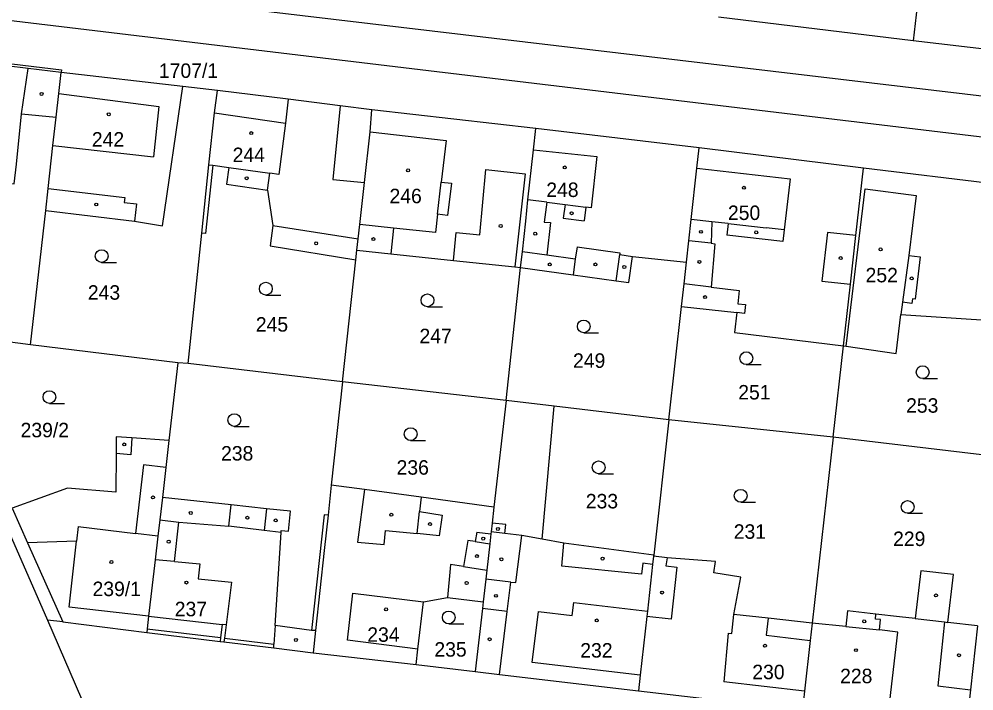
# Model space of a CAD drawing. Extents: x -724107 to -720612, y -1045267 to -1038441.
# Drawn here: x -722932.3 to -722820.2, y -1042174.7 to -1042095.8 of the extents above; entities that cross this region are included whole.
import ezdxf

# ---------------------------------------------------------------- set-up
doc = ezdxf.new("R2010")
doc.units = 0
for name, color, linetype in [('Hranice parcel', 7, 'Continuous'), ('Parcelní čísla', 7, 'Continuous'), ('Vnitřní kresba', 7, 'Continuous'), ('Značky budov', 7, 'Continuous'), ('Značky kultur', 7, 'Continuous')]:
    doc.layers.add(name, color=color, linetype=linetype)

msp = doc.modelspace()

# ---------------------------------------------------------------- linework, layer by layer
at = {"layer": 'Hranice parcel'}
for p, q in [((-722823.15, -1042063.63), (-722827.33, -1042098.38)), ((-722961.44, -1042092.63), (-722614.7, -1042134.22)), ((-722827.33, -1042098.38), (-722850.16, -1042095.63)), ((-722958.94, -1042098.3), (-722928.96, -1042166.43)), ((-722810.31, -1042100.42), (-722827.33, -1042098.38)), ((-722913.09, -1042103.75), (-722927.35, -1042102.12)), ((-722909.01, -1042104.22), (-722913.09, -1042103.75)), ((-722871.64, -1042108.71), (-722890.9, -1042106.49)), ((-722852.44, -1042110.98), (-722871.64, -1042108.71)), ((-722833.16, -1042113.36), (-722852.44, -1042110.98)), ((-722814.35, -1042115.64), (-722833.16, -1042113.36)), ((-722930.96, -1042134.09), (-722929.17, -1042118.32)), ((-722892.75, -1042124.1), (-722892.63, -1042123)), ((-722894.33, -1042138.46), (-722892.75, -1042124.1)), ((-722875.11, -1042140.62), (-722873.41, -1042125.02)), ((-722856, -1042142.89), (-722854.52, -1042129.59)), ((-722930.96, -1042134.09), (-722942.26, -1042132.6)), ((-722913.66, -1042136.23), (-722930.96, -1042134.09)), ((-722836.71, -1042144.96), (-722835.5, -1042134.21)), ((-722913.66, -1042136.23), (-722914.71, -1042145.34)), ((-722912.46, -1042136.29), (-722913.66, -1042136.23)), ((-722894.33, -1042138.46), (-722912.46, -1042136.29)), ((-722894.33, -1042138.46), (-722895.65, -1042150.57)), ((-722875.11, -1042140.62), (-722894.33, -1042138.46)), ((-722875.11, -1042140.62), (-722876.54, -1042153.16)), ((-722869.47, -1042141.29), (-722875.11, -1042140.62)), ((-722856, -1042142.89), (-722869.47, -1042141.29)), ((-722856, -1042142.89), (-722857.79, -1042158.79)), ((-722836.71, -1042144.96), (-722856, -1042142.89)), ((-722836.71, -1042144.96), (-722839.18, -1042166.79)), ((-722817.33, -1042147.24), (-722836.71, -1042144.96)), ((-722857.79, -1042158.79), (-722857.81, -1042158.94)), ((-722927.18, -1042166.65), (-722928.96, -1042166.43)), ((-722928.96, -1042166.43), (-722924.33, -1042177.14)), ((-722927.18, -1042166.65), (-722917.31, -1042167.89)), ((-722897.51, -1042167.65), (-722897.79, -1042170.26)), ((-722897.79, -1042170.26), (-722885.69, -1042171.66)), ((-722885.69, -1042171.66), (-722878.74, -1042172.47)), ((-722859.57, -1042174.72), (-722840.31, -1042176.96))]:
    msp.add_line(p, q, dxfattribs=at)
for points in [[(-722957.38, -1042098.49), (-722957.5, -1042098.17), (-722927.33, -1042101.81), (-722927.35, -1042102.12)], [(-722941.44, -1042100.39), (-722942.83, -1042111.63), (-722939.2, -1042112.07), (-722939.41, -1042113.91), (-722938.26, -1042114.08), (-722938.3, -1042114.55), (-722934.94, -1042114.87), (-722932.89, -1042115.21), (-722932.59, -1042112.9), (-722932.01, -1042106.98), (-722927.96, -1042107.37)], [(-722927.35, -1042102.12), (-722931.22, -1042101.64), (-722941.44, -1042100.39)], [(-722927.96, -1042107.37), (-722927.64, -1042104.6), (-722927.35, -1042102.12)], [(-722929.17, -1042118.32), (-722918.76, -1042119.59), (-722915.45, -1042120.13), (-722913.09, -1042103.75)], [(-722910.01, -1042112.95), (-722909.37, -1042106.86), (-722909.01, -1042104.22)], [(-722890.9, -1042106.49), (-722894.61, -1042106.02), (-722900.7, -1042105.26), (-722909.01, -1042104.22)], [(-722892.63, -1042123), (-722892.48, -1042121.67), (-722892.29, -1042119.97), (-722891.75, -1042115.04), (-722891.09, -1042109.07), (-722890.9, -1042106.49)], [(-722929.17, -1042118.32), (-722928.88, -1042115.73), (-722928.34, -1042110.68), (-722927.96, -1042107.37)], [(-722873.41, -1042125.02), (-722873.21, -1042123.16), (-722872.82, -1042119.59), (-722872.55, -1042117.08), (-722871.92, -1042111.21), (-722871.64, -1042108.71)], [(-722853.93, -1042124.38), (-722853.66, -1042121.88), (-722853.38, -1042119.37), (-722852.71, -1042113.37), (-722852.44, -1042110.98)], [(-722912.46, -1042136.29), (-722910.85, -1042120.98), (-722910.01, -1042112.95)], [(-722910.01, -1042112.95), (-722909.56, -1042113.01), (-722907.68, -1042113.27), (-722907.96, -1042115.25), (-722903.14, -1042115.92), (-722902.5, -1042120.1), (-722902.84, -1042122.49), (-722892.75, -1042124.1)], [(-722835.5, -1042134.21), (-722834.69, -1042126.98), (-722834.05, -1042121.27), (-722833.16, -1042113.36)], [(-722892.63, -1042123), (-722888.65, -1042123.42), (-722881.31, -1042124.19), (-722874.11, -1042124.95), (-722873.41, -1042125.02)], [(-722873.41, -1042125.02), (-722867.25, -1042125.88), (-722862.2, -1042126.58), (-722860.72, -1042126.79), (-722860.29, -1042123.71), (-722853.93, -1042124.38)], [(-722854.52, -1042129.59), (-722854.22, -1042126.93), (-722853.93, -1042124.38)], [(-722854.52, -1042129.59), (-722848.02, -1042130.31), (-722848.28, -1042132.66), (-722835.5, -1042134.21)], [(-722835.5, -1042134.21), (-722835.2, -1042134.25), (-722829.33, -1042135.11), (-722828.75, -1042130.54), (-722817.52, -1042131.27), (-722816.05, -1042131.41)], [(-722857.79, -1042158.79), (-722868.35, -1042157.41), (-722870.88, -1042156.94), (-722869.47, -1042141.29)], [(-722914.71, -1042145.34), (-722919.05, -1042145.02), (-722920.9, -1042144.89), (-722920.92, -1042146.88), (-722920.96, -1042151.42), (-722926.61, -1042150.94), (-722933.1, -1042153.28)], [(-722914.71, -1042145.34), (-722915.07, -1042148.51), (-722915.48, -1042152.05)], [(-722895.65, -1042150.57), (-722896.03, -1042154.12), (-722896.49, -1042158.27), (-722897.51, -1042167.65)], [(-722876.54, -1042153.16), (-722885.09, -1042152), (-722891.73, -1042151.1), (-722895.65, -1042150.57)], [(-722915.48, -1042152.05), (-722915.79, -1042154.67), (-722916, -1042156.56), (-722916.33, -1042159.36), (-722917.09, -1042165.96), (-722917.26, -1042167.44), (-722917.31, -1042167.89)], [(-722897.51, -1042167.65), (-722897.95, -1042167.64), (-722902.24, -1042167.08), (-722901.53, -1042156.13), (-722901.52, -1042155.91), (-722900.66, -1042156), (-722900.42, -1042153.65), (-722903.26, -1042153.35), (-722907.41, -1042152.91), (-722915.48, -1042152.05)], [(-722933.1, -1042153.28), (-722931.3, -1042157.34), (-722927.18, -1042166.65)], [(-722876.54, -1042153.16), (-722876.76, -1042155.03), (-722876.88, -1042156.05), (-722876.9, -1042156.29), (-722877.03, -1042157.48), (-722877.38, -1042160.56), (-722877.51, -1042161.62), (-722877.8, -1042164.27)], [(-722857.81, -1042158.94), (-722857.91, -1042159.88), (-722858.53, -1042165.39), (-722858.6, -1042166), (-722859.38, -1042172.91), (-722859.57, -1042174.72)], [(-722839.18, -1042166.79), (-722844.35, -1042166.21), (-722848.38, -1042165.76), (-722847.57, -1042161.37), (-722850.74, -1042160.88), (-722850.53, -1042159.56), (-722856.21, -1042159.12), (-722857.81, -1042158.94)], [(-722819.76, -1042167.1), (-722823.26, -1042166.71), (-722822.6, -1042161.07), (-722826.41, -1042160.63), (-722827.07, -1042166.26), (-722828.92, -1042166.04), (-722831.69, -1042165.72), (-722835.02, -1042165.33), (-722835.24, -1042167.2), (-722839.18, -1042166.79)], [(-722885.69, -1042171.66), (-722885.47, -1042169.83), (-722884.8, -1042164.28), (-722881.99, -1042163.76), (-722877.8, -1042164.27)], [(-722877.8, -1042164.27), (-722877.9, -1042165.07), (-722878.74, -1042172.47)], [(-722839.18, -1042166.79), (-722839.41, -1042168.81), (-722840.08, -1042174.77), (-722840.31, -1042176.96)], [(-722819.76, -1042167.1), (-722820.58, -1042174.6), (-722821.09, -1042179.25)], [(-722917.31, -1042167.89), (-722908.71, -1042168.94), (-722908.26, -1042168.99), (-722902.41, -1042169.7), (-722897.79, -1042170.26)], [(-722878.74, -1042172.47), (-722875.91, -1042172.8), (-722859.57, -1042174.72)]]:
    msp.add_lwpolyline(points, dxfattribs=at)
at = {"layer": 'Vnitřní kresba'}
for p, q in [((-722788.05, -1042108.59), (-722963.56, -1042087.8)), ((-722932.01, -1042106.98), (-722931.22, -1042101.64)), ((-722927.64, -1042104.6), (-722915.89, -1042106.1)), ((-722900.7, -1042105.26), (-722901.02, -1042108.05)), ((-722915.89, -1042106.1), (-722916.53, -1042112.04)), ((-722894.61, -1042106.02), (-722895.48, -1042114.67)), ((-722909.37, -1042106.86), (-722901.02, -1042108.05)), ((-722901.02, -1042108.05), (-722901.8, -1042114.09)), ((-722891.09, -1042109.07), (-722882.16, -1042110.12)), ((-722928.34, -1042110.68), (-722916.53, -1042112.04)), ((-722882.16, -1042110.12), (-722882.73, -1042114.99)), ((-722871.92, -1042111.21), (-722864.45, -1042112)), ((-722864.45, -1042112), (-722865.11, -1042118.02)), ((-722909.56, -1042113.01), (-722910.41, -1042121.02)), ((-722907.68, -1042113.27), (-722902.87, -1042113.94)), ((-722852.71, -1042113.37), (-722841.75, -1042114.62)), ((-722903.14, -1042115.92), (-722902.87, -1042113.94)), ((-722901.8, -1042114.09), (-722902.87, -1042113.94)), ((-722878.22, -1042121.2), (-722877.49, -1042113.51)), ((-722877.49, -1042113.51), (-722872.87, -1042114.01)), ((-722872.87, -1042114.01), (-722874.11, -1042124.95)), ((-722895.48, -1042114.67), (-722891.75, -1042115.04)), ((-722883.17, -1042118.76), (-722882.73, -1042114.99)), ((-722882.73, -1042114.99), (-722881.54, -1042115.13)), ((-722881.54, -1042115.13), (-722881.98, -1042118.9)), ((-722841.75, -1042114.62), (-722842.48, -1042120.61)), ((-722928.88, -1042115.73), (-722919.89, -1042116.79)), ((-722919.89, -1042116.79), (-722919.96, -1042117.4)), ((-722835.2, -1042134.25), (-722832.96, -1042115.78)), ((-722832.96, -1042115.78), (-722826.97, -1042116.57)), ((-722826.97, -1042116.57), (-722827.84, -1042123.59)), ((-722919.96, -1042117.4), (-722918.53, -1042117.53)), ((-722918.53, -1042117.53), (-722918.76, -1042119.59)), ((-722870.34, -1042117.36), (-722872.55, -1042117.08)), ((-722870.34, -1042117.36), (-722870.63, -1042119.71)), ((-722870.34, -1042117.36), (-722868.2, -1042117.63)), ((-722868.2, -1042117.63), (-722868.4, -1042119.22)), ((-722868.2, -1042117.63), (-722865.77, -1042117.94)), ((-722865.77, -1042117.94), (-722865.97, -1042119.54)), ((-722865.11, -1042118.02), (-722865.77, -1042117.94)), ((-722883.17, -1042118.76), (-722883.42, -1042120.91)), ((-722881.98, -1042118.9), (-722883.17, -1042118.76)), ((-722902.5, -1042120.1), (-722892.48, -1042121.67)), ((-722888.33, -1042120.39), (-722892.29, -1042119.97)), ((-722870.63, -1042119.71), (-722869.9, -1042119.75)), ((-722869.9, -1042119.75), (-722870.33, -1042123.56)), ((-722868.4, -1042119.22), (-722865.97, -1042119.54)), ((-722850.98, -1042119.64), (-722853.38, -1042119.37)), ((-722850.98, -1042119.64), (-722851.02, -1042122.18)), ((-722849.03, -1042119.87), (-722850.98, -1042119.64)), ((-722849.03, -1042119.87), (-722849.18, -1042121.21)), ((-722849.03, -1042119.87), (-722844.59, -1042120.37)), ((-722910.41, -1042121.02), (-722910.85, -1042120.98)), ((-722888.33, -1042120.39), (-722888.65, -1042123.42)), ((-722883.42, -1042120.91), (-722888.33, -1042120.39)), ((-722881.31, -1042124.19), (-722880.97, -1042120.91)), ((-722880.97, -1042120.91), (-722878.22, -1042121.2)), ((-722842.64, -1042121.96), (-722849.18, -1042121.21)), ((-722842.48, -1042120.61), (-722844.59, -1042120.37)), ((-722842.48, -1042120.61), (-722842.64, -1042121.96)), ((-722837.37, -1042120.9), (-722838.03, -1042126.61)), ((-722834.05, -1042121.27), (-722837.37, -1042120.9)), ((-722851.02, -1042122.18), (-722853.66, -1042121.88)), ((-722851.02, -1042122.18), (-722850.62, -1042122.23)), ((-722850.62, -1042122.23), (-722851.02, -1042127.32)), ((-722870.33, -1042123.56), (-722873.21, -1042123.16)), ((-722866.79, -1042122.58), (-722866.99, -1042124.03)), ((-722866.79, -1042122.58), (-722861.75, -1042123.29)), ((-722862.2, -1042126.58), (-722861.78, -1042123.5)), ((-722861.75, -1042123.29), (-722861.78, -1042123.5)), ((-722861.78, -1042123.5), (-722860.29, -1042123.71)), ((-722866.99, -1042124.03), (-722870.33, -1042123.56)), ((-722866.99, -1042124.03), (-722867.25, -1042125.88)), ((-722827.84, -1042123.59), (-722828.56, -1042129.1)), ((-722827.84, -1042123.59), (-722826.49, -1042123.75)), ((-722826.49, -1042123.75), (-722827.1, -1042128.75)), ((-722838.03, -1042126.61), (-722834.69, -1042126.98)), ((-722851.02, -1042127.32), (-722854.22, -1042126.93)), ((-722851.02, -1042127.32), (-722847.74, -1042127.72)), ((-722847.74, -1042127.72), (-722847.91, -1042129.28)), ((-722828.56, -1042129.1), (-722828.75, -1042130.54)), ((-722827.49, -1042129.24), (-722828.56, -1042129.1)), ((-722827.4, -1042128.71), (-722827.49, -1042129.24)), ((-722827.1, -1042128.75), (-722827.4, -1042128.71)), ((-722847.91, -1042129.28), (-722847.01, -1042129.38)), ((-722847.01, -1042129.38), (-722847.12, -1042130.41)), ((-722847.12, -1042130.41), (-722848.02, -1042130.31)), ((-722919.05, -1042145.02), (-722919.2, -1042147.01)), ((-722919.2, -1042147.01), (-722920.92, -1042146.88)), ((-722917.71, -1042148.21), (-722918.63, -1042156.25)), ((-722915.07, -1042148.51), (-722917.71, -1042148.21)), ((-722891.73, -1042151.1), (-722892.56, -1042157.27)), ((-722885.09, -1042152), (-722885.27, -1042153.69)), ((-722907.67, -1042155.41), (-722907.41, -1042152.91)), ((-722903.26, -1042153.35), (-722903.53, -1042155.92)), ((-722885.55, -1042156.26), (-722885.27, -1042153.69)), ((-722885.27, -1042153.69), (-722882.63, -1042154.11)), ((-722915.79, -1042154.67), (-722913.53, -1042154.91)), ((-722914.04, -1042159.53), (-722913.53, -1042154.91)), ((-722913.53, -1042154.91), (-722907.67, -1042155.41)), ((-722896.48, -1042154.07), (-722897.95, -1042167.64)), ((-722896.03, -1042154.12), (-722896.48, -1042154.07)), ((-722882.63, -1042154.11), (-722882.99, -1042156.52)), ((-722925.38, -1042155.45), (-722925.56, -1042157.14)), ((-722925.38, -1042155.45), (-722918.63, -1042156.25)), ((-722903.53, -1042155.92), (-722907.67, -1042155.41)), ((-722901.53, -1042156.13), (-722903.53, -1042155.92)), ((-722889.43, -1042157.55), (-722889.28, -1042155.92)), ((-722889.28, -1042155.92), (-722885.55, -1042156.26)), ((-722875.27, -1042156.25), (-722876.88, -1042156.05)), ((-722875.14, -1042155.21), (-722876.76, -1042155.03)), ((-722875.27, -1042156.25), (-722875.14, -1042155.21)), ((-722925.56, -1042157.14), (-722931.3, -1042157.34)), ((-722926.41, -1042164.91), (-722925.56, -1042157.14)), ((-722916, -1042156.56), (-722918.63, -1042156.25)), ((-722882.99, -1042156.52), (-722885.55, -1042156.26)), ((-722879.63, -1042157.07), (-722880.11, -1042160.14)), ((-722878.75, -1042157.21), (-722879.63, -1042157.07)), ((-722878.56, -1042156.1), (-722878.75, -1042157.21)), ((-722878.56, -1042156.1), (-722876.9, -1042156.29)), ((-722873.28, -1042156.5), (-722875.27, -1042156.25)), ((-722873.97, -1042162.03), (-722873.28, -1042156.5)), ((-722870.88, -1042156.94), (-722873.28, -1042156.5)), ((-722892.56, -1042157.27), (-722889.43, -1042157.55)), ((-722878.75, -1042157.21), (-722877.03, -1042157.48)), ((-722868.58, -1042160.11), (-722868.35, -1042157.41)), ((-722914.04, -1042159.53), (-722916.33, -1042159.36)), ((-722856.21, -1042159.12), (-722856.38, -1042160.06)), ((-722914.04, -1042159.53), (-722911.09, -1042159.83)), ((-722911.09, -1042159.83), (-722911.29, -1042161.58)), ((-722881.69, -1042160.35), (-722881.99, -1042163.76)), ((-722881.64, -1042159.9), (-722881.69, -1042160.35)), ((-722880.11, -1042160.14), (-722881.64, -1042159.9)), ((-722880.11, -1042160.14), (-722877.38, -1042160.56)), ((-722859.2, -1042161.04), (-722868.58, -1042160.11)), ((-722859.07, -1042159.75), (-722859.2, -1042161.04)), ((-722857.91, -1042159.88), (-722859.07, -1042159.75)), ((-722856.38, -1042160.06), (-722855.08, -1042160.2)), ((-722855.08, -1042160.2), (-722855.75, -1042166.32)), ((-722911.29, -1042161.58), (-722907.35, -1042161.99)), ((-722874.56, -1042161.96), (-722877.51, -1042161.62)), ((-722907.35, -1042161.99), (-722908, -1042166.99)), ((-722874.99, -1042165.4), (-722874.56, -1042161.96)), ((-722874.56, -1042161.96), (-722873.97, -1042162.03)), ((-722893.75, -1042168.79), (-722893.11, -1042163.27)), ((-722893.11, -1042163.27), (-722884.8, -1042164.28)), ((-722917.09, -1042165.96), (-722926.41, -1042164.91)), ((-722867.36, -1042165.87), (-722867.18, -1042164.35)), ((-722867.18, -1042164.35), (-722858.53, -1042165.39)), ((-722917.09, -1042165.96), (-722908.45, -1042166.94)), ((-722874.99, -1042165.4), (-722877.9, -1042165.07)), ((-722875.91, -1042172.8), (-722874.99, -1042165.4)), ((-722872.04, -1042171.42), (-722871.33, -1042165.4)), ((-722871.33, -1042165.4), (-722867.36, -1042165.87)), ((-722855.75, -1042166.32), (-722858.6, -1042166)), ((-722848.63, -1042168.01), (-722848.38, -1042165.76)), ((-722831.76, -1042166.3), (-722831.69, -1042165.72)), ((-722908.45, -1042166.94), (-722908.65, -1042168.49)), ((-722908, -1042166.99), (-722908.45, -1042166.94)), ((-722908, -1042166.99), (-722908.2, -1042168.54)), ((-722902.24, -1042167.08), (-722902.39, -1042169.25)), ((-722844.35, -1042166.21), (-722844.58, -1042168.19)), ((-722835.24, -1042167.2), (-722831.29, -1042167.59)), ((-722831.15, -1042166.37), (-722831.76, -1042166.3)), ((-722831.29, -1042167.59), (-722831.15, -1042166.37)), ((-722827.07, -1042166.26), (-722823.63, -1042166.65)), ((-722823.63, -1042166.65), (-722824.43, -1042174.13)), ((-722823.63, -1042166.65), (-722823.26, -1042166.71)), ((-722917.26, -1042167.44), (-722908.65, -1042168.49)), ((-722849.03, -1042167.97), (-722849.55, -1042173.68)), ((-722849.03, -1042167.97), (-722848.63, -1042168.01)), ((-722844.58, -1042168.19), (-722839.41, -1042168.81)), ((-722829.11, -1042167.84), (-722831.29, -1042167.59)), ((-722830.05, -1042175.94), (-722829.11, -1042167.84)), ((-722908.65, -1042168.49), (-722908.71, -1042168.94)), ((-722908.2, -1042168.54), (-722908.26, -1042168.99)), ((-722908.2, -1042168.54), (-722902.39, -1042169.25)), ((-722902.41, -1042169.7), (-722902.39, -1042169.25)), ((-722885.47, -1042169.83), (-722893.75, -1042168.79)), ((-722859.38, -1042172.91), (-722872.04, -1042171.42)), ((-722840.08, -1042174.77), (-722849.55, -1042173.68)), ((-722824.43, -1042174.13), (-722820.58, -1042174.6))]:
    msp.add_line(p, q, dxfattribs=at)
at = {"layer": 'Značky budov'}
for centre in [(-722929.66, -1042104.64), (-722921.77, -1042107.03), (-722905.05, -1042109.23), (-722886.62, -1042113.61), (-722868.23, -1042113.27), (-722905.58, -1042114.54), (-722847.2, -1042115.65), (-722923.25, -1042117.62), (-722867.42, -1042118.65), (-722875.75, -1042120.15), (-722871.7, -1042121.05), (-722852.25, -1042120.83), (-722845.75, -1042120.89), (-722897.42, -1042122.18), (-722890.69, -1042121.69), (-722831.15, -1042122.89), (-722869.99, -1042124.66), (-722864.63, -1042124.66), (-722852.42, -1042124.36), (-722835.83, -1042123.92), (-722861.24, -1042124.96), (-722827.49, -1042126.3), (-722851.75, -1042128.49), (-722919.96, -1042145.8), (-722916.58, -1042152.02), (-722912.15, -1042153.85), (-722905.5, -1042154.41), (-722902.17, -1042154.72), (-722888.6, -1042154.06), (-722884.05, -1042155.16), (-722876.08, -1042155.73), (-722914.74, -1042157.22), (-722877.8, -1042156.86), (-722878.55, -1042158.91), (-722875.67, -1042159.29), (-722863.79, -1042159.21), (-722921.46, -1042159.61), (-722912.65, -1042162.02), (-722879.75, -1042162.07), (-722876.32, -1042163.58), (-722856.8, -1042163.2), (-722824.64, -1042163.53), (-722889.21, -1042165.17), (-722864.47, -1042166.47), (-722833.07, -1042166.58), (-722899.8, -1042168.76), (-722877.05, -1042168.67), (-722844.72, -1042169.45), (-722834.05, -1042169.96), (-722821.94, -1042170.56)]:
    msp.add_circle(centre, 0.175, dxfattribs=at)
at = {"layer": 'Značky kultur'}
for p, q in [((-722922.61, -1042124.43), (-722920.86, -1042124.43)), ((-722903.33, -1042128.26), (-722901.58, -1042128.26)), ((-722884.35, -1042129.62), (-722882.6, -1042129.62)), ((-722866, -1042132.69), (-722864.25, -1042132.69)), ((-722846.91, -1042136.42), (-722845.16, -1042136.42)), ((-722826.2, -1042138.06), (-722824.45, -1042138.06)), ((-722928.74, -1042140.99), (-722926.99, -1042140.99)), ((-722907.03, -1042143.69), (-722905.28, -1042143.69)), ((-722886.33, -1042145.34), (-722884.58, -1042145.34)), ((-722864.25, -1042149.24), (-722862.5, -1042149.24)), ((-722847.57, -1042152.58), (-722845.82, -1042152.58)), ((-722827.97, -1042153.89), (-722826.22, -1042153.89)), ((-722881.85, -1042166.87), (-722880.1, -1042166.87))]:
    msp.add_line(p, q, dxfattribs=at)
for centre in [(-722922.61, -1042123.68), (-722903.33, -1042127.51), (-722884.35, -1042128.87), (-722866, -1042131.94), (-722846.91, -1042135.67), (-722826.2, -1042137.31), (-722928.74, -1042140.24), (-722907.03, -1042142.94), (-722886.33, -1042144.59), (-722864.25, -1042148.49), (-722847.57, -1042151.83), (-722827.97, -1042153.14), (-722881.85, -1042166.12)]:
    msp.add_circle(centre, 0.75, dxfattribs=at)

# ---------------------------------------------------------------- texts
at = {"layer": 'Parcelní čísla'}
for s, p in [('1707/1', (-722915.89, -1042102.75)), ('242', (-722923.76, -1042110.82)), ('244', (-722907.23, -1042112.64)), ('248', (-722870.4, -1042116.74)), ('246', (-722888.81, -1042117.47)), ('250', (-722849.07, -1042119.44)), ('252', (-722832.91, -1042126.76)), ('243', (-722924.23, -1042128.8)), ('245', (-722904.51, -1042132.55)), ('247', (-722885.29, -1042133.91)), ('249', (-722867.26, -1042136.8)), ('251', (-722847.86, -1042140.52)), ('253', (-722828.15, -1042142.07)), ('239/2', (-722932.13, -1042144.96)), ('238', (-722908.59, -1042147.69)), ('236', (-722887.98, -1042149.35)), ('233', (-722865.76, -1042153.31)), ('231', (-722848.39, -1042156.88)), ('229', (-722829.68, -1042157.73)), ('239/1', (-722923.68, -1042163.61)), ('237', (-722914.03, -1042165.98)), ('234', (-722891.42, -1042168.98)), ('235', (-722883.54, -1042170.72)), ('232', (-722866.41, -1042170.83)), ('230', (-722846.21, -1042173.37)), ('228', (-722835.9, -1042173.84))]:
    msp.add_text(s, height=1.7, dxfattribs=at).set_placement(p)

doc.saveas('drawing.dxf')
